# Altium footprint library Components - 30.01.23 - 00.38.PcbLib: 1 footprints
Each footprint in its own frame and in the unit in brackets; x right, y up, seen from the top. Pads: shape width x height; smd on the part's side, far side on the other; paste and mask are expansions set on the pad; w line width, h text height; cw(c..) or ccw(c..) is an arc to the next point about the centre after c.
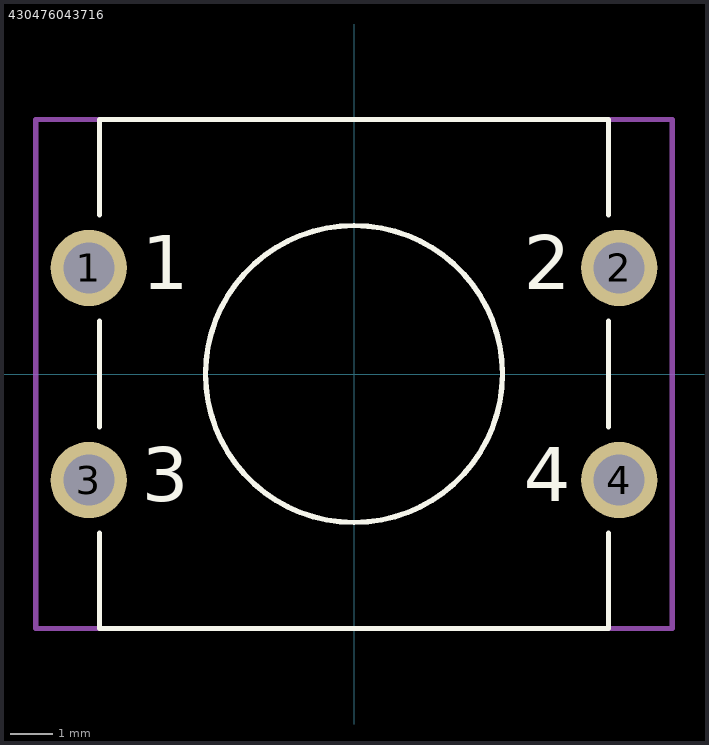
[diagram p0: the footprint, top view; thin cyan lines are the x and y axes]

## 430476043716 [mm] "12*12mm vertical type,THT,  height 4.3mm, white actuator, 160gf, Bulk"
height 4.3
pads (4):
  round 1.8 hole 1.2: 1(-6.25,2.5) 2(6.25,2.5) 3(-6.25,-2.5) 4(6.25,-2.5)
Top Overlay:
  circle w0.127: c0,0 r3.5
  lines w0.127: -6,-3.75 -6,-6 ; -6,-1.25 -6,1.25 ; -6,3.75 -6,6 ; 6,-3.75 6,-6 ; 6,-1.25 6,1.25 ; 6,3.75 6,6 ; -6,-6 6,-6 ; -6,-6 6,-6 ; -6,6 6,6 ; -6,6 6,6
  text "4" at 4,-3 h1.27
  text "3" at -5,-3 h1.27
  text "2" at 4,2 h1.27
  text "1" at -5,2 h1.27
Mechanical 15:
  lines w0.127: -7.5,-6 -7.5,6 7.5,6 7.5,-6 -7.5,-6
3D body "4304x60xx7x6.stp": height 4.4, standoff -3.4, extent -6.985,-6 6.986,6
